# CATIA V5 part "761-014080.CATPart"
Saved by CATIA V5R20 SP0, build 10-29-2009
Part number: 761-014080
Source: Unknown
Property "ARTICLENO": "761-014080"
Property "BOMINFO": "761-014080"
Property "CODE": "761-014080"
Property "H": "14.000"
Property "L1": "80.000"
Property "L2": "50.000"
Property "LINA": "761-014080"
Property "NB": "761-014080"
Property "NBSYN": "$CODE."
Property "NN": "761"
Property "NT": "VW/AUDI Keys"
Property "P": "0.000"
Property "SUPPLIER": "CF"
Bounding box of the stored display mesh (mm): x -40 to 40, y 0 to 14, z -11 to 11
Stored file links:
  C:\Users\Utente\Desktop\3D files 761\761-014080.CATPart
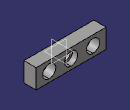
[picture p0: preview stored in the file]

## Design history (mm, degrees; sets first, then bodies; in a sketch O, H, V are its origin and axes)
Body1 "Geometry.1" (main body)
  Solid1 "761-014080.catpart": solid without history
